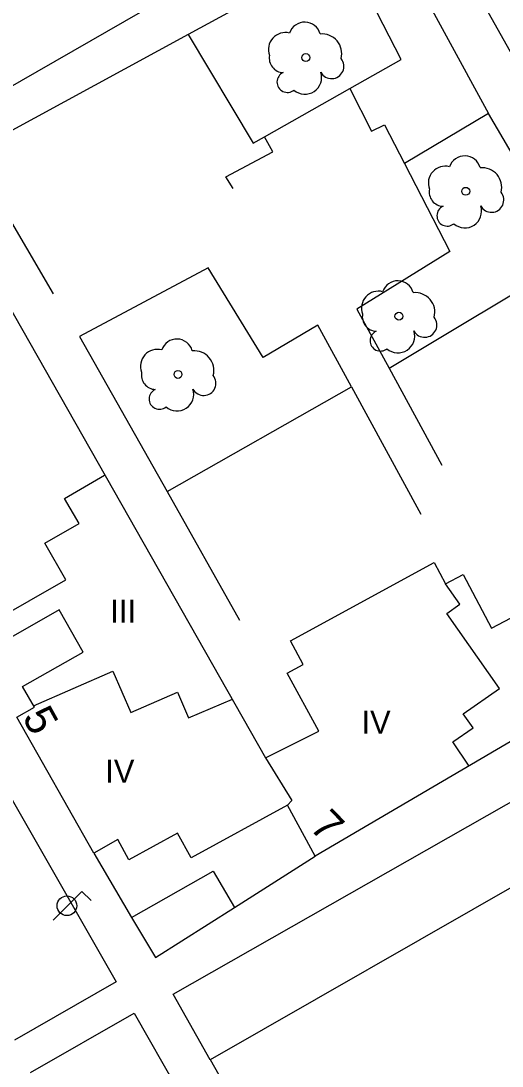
# Model space of a CAD drawing. Extents: x 282771 to 285132, y 4823109 to 4825496.
# Drawn here: x 283735.3 to 283766.5, y 4823641.9 to 4823709.7 of the extents above; entities that cross this region are included whole.
import ezdxf

# ---------------------------------------------------------------- set-up
doc = ezdxf.new("R2010")
doc.units = 0
for name, color, linetype in [('ACERA-INTERIOR', 7, 'Continuous'), ('ARBOL', 7, 'Continuous'), ('EDIFICIO', 7, 'Continuous'), ('FAROLA', 7, 'Continuous'), ('MEDIANERA', 7, 'Continuous'), ('NUM-PORTAL', 7, 'Continuous'), ('TXT-ALTURA-EDIFICIO', 7, 'Continuous'), ('ZONA-VERDE', 7, 'Continuous')]:
    doc.layers.add(name, color=color, linetype=linetype)

msp = doc.modelspace()

# ---------------------------------------------------------------- linework, layer by layer
at = {"layer": 'ACERA-INTERIOR'}
for points in [[(283760.017, 4823714.081), (283765.64, 4823703.742)], [(283746.148, 4823708.866), (283732.013, 4823701.173), (283737.392, 4823692.038)], [(283756.642, 4823705.36), (283758.048, 4823702.585), (283758.894, 4823703.008), (283760.191, 4823700.481)], [(283749.062, 4823698.858), (283748.58, 4823699.624), (283751.635, 4823701.256), (283751.098, 4823702.224)], [(283759.18, 4823687.213), (283762.612, 4823680.898)], [(283756.744, 4823685.989), (283761.242, 4823677.728)], [(283744.776, 4823679.19), (283749.482, 4823670.838)], [(283747.58, 4823642.322), (283758.962, 4823622.208), (283786.649, 4823638.022), (283775.243, 4823658.175)], [(283742.475, 4823651.555), (283744.014, 4823648.938), (283749.15, 4823652.194)]]:
    msp.add_lwpolyline(points, dxfattribs=at)
at = {"layer": 'ARBOL'}
for centre in [(283753.782, 4823707.367), (283764.162, 4823698.688), (283759.822, 4823690.578), (283745.482, 4823686.798)]:
    msp.add_circle(centre, 0.255, dxfattribs=at)
for centre, radius, start, end in [((283753.712, 4823708.627), 1.038, 15.64228, 161.38435), ((283752.452, 4823707.897), 1.097, 75.4318, 200.55608), ((283754.842, 4823707.627), 1.272, 345.03273, 95.79925), ((283752.342, 4823707.327), 0.935, 168.59898, 268.13236), ((283755.452, 4823706.797), 0.797, 208.96246, 38.99103), ((283752.582, 4823705.777), 0.672, 113.73672, 309.4725), ((283753.722, 4823706.077), 1.086, 228.95447, 17.92796), ((283764.092, 4823699.948), 1.038, 15.64228, 161.38435), ((283762.832, 4823699.218), 1.097, 75.4318, 200.55608), ((283765.222, 4823698.948), 1.272, 345.03273, 95.79925), ((283762.722, 4823698.648), 0.935, 168.59898, 268.13236), ((283765.832, 4823698.118), 0.797, 208.96246, 38.99103), ((283762.962, 4823697.098), 0.672, 113.73672, 309.4725), ((283764.102, 4823697.398), 1.086, 228.95447, 17.92796), ((283759.752, 4823691.838), 1.038, 15.64228, 161.38435), ((283758.492, 4823691.108), 1.097, 75.4318, 200.55608), ((283760.882, 4823690.838), 1.272, 345.03273, 95.79925), ((283758.382, 4823690.538), 0.935, 168.59898, 268.13236), ((283761.492, 4823690.008), 0.797, 208.96246, 38.99103), ((283745.412, 4823688.058), 1.038, 15.64228, 161.38435), ((283758.622, 4823688.988), 0.672, 113.73672, 309.4725), ((283759.762, 4823689.288), 1.086, 228.95447, 17.92796), ((283744.152, 4823687.328), 1.097, 75.4318, 200.55608), ((283746.542, 4823687.058), 1.272, 345.03273, 95.79925), ((283744.042, 4823686.758), 0.935, 168.59898, 268.13236), ((283747.152, 4823686.228), 0.797, 208.96246, 38.99103), ((283744.282, 4823685.208), 0.672, 113.73672, 309.4725), ((283745.422, 4823685.508), 1.086, 228.95447, 17.92796)]:
    msp.add_arc(centre, radius, start, end, dxfattribs=at)
at = {"layer": 'EDIFICIO'}
for points in [[(283767.562, 4823706.857), (283762.582, 4823715.717), (283765.512, 4823717.367), (283764.712, 4823718.787), (283767.492, 4823720.377), (283765.782, 4823723.377), (283728.422, 4823701.918), (283751.172, 4823661.918), (283754.622, 4823663.638), (283752.572, 4823667.398), (283753.612, 4823667.968), (283752.782, 4823669.498), (283762.102, 4823674.588), (283762.852, 4823673.198), (283763.992, 4823673.808), (283765.842, 4823670.328), (283769.622, 4823672.328)], [(283772.802, 4823666.318), (283754.392, 4823655.518), (283752.592, 4823658.828), (283746.332, 4823655.408), (283745.452, 4823657.018), (283742.302, 4823655.278), (283741.572, 4823656.598), (283740.022, 4823655.728), (283735.032, 4823664.558), (283736.162, 4823665.198), (283735.402, 4823666.548), (283739.322, 4823668.768), (283737.772, 4823671.508), (283734.172, 4823669.458)]]:
    msp.add_lwpolyline(points, dxfattribs=at)
at = {"layer": 'FAROLA'}
for p, q in [((283739.252, 4823653.238), (283738.312, 4823652.308)), ((283739.842, 4823652.648), (283739.252, 4823653.238)), ((283738.312, 4823652.308), (283737.382, 4823651.368))]:
    msp.add_line(p, q, dxfattribs=at)
msp.add_circle((283738.272, 4823652.308), 0.637, dxfattribs=at)
at = {"layer": 'MEDIANERA'}
for points in [[(283733.432, 4823670.748), (283738.202, 4823673.458), (283736.832, 4823675.848), (283739.062, 4823677.128), (283738.122, 4823678.748), (283740.722, 4823680.258)], [(283764.382, 4823661.378), (283763.312, 4823662.938), (283764.632, 4823663.858), (283764.002, 4823664.768), (283766.352, 4823666.418), (283762.942, 4823671.288), (283763.782, 4823671.878), (283762.852, 4823673.198)], [(283736.102, 4823665.288), (283741.262, 4823667.538), (283742.422, 4823664.858), (283745.452, 4823666.168), (283746.172, 4823664.498), (283749.022, 4823665.718)], [(283751.172, 4823661.918), (283752.882, 4823659.138), (283752.592, 4823658.828)]]:
    msp.add_lwpolyline(points, dxfattribs=at)
at = {"layer": 'ZONA-VERDE'}
for p, q in [((283731.619, 4823664.587), (283741.472, 4823647.361)), ((283745.162, 4823646.562), (283772.871, 4823662.333)), ((283775.234, 4823658.159), (283747.57, 4823642.306)), ((283741.472, 4823647.361), (283734.87, 4823643.585)), ((283747.57, 4823642.306), (283745.162, 4823646.562)), ((283735.912, 4823641.491), (283742.632, 4823645.331)), ((283742.632, 4823645.331), (283753.252, 4823626.741))]:
    msp.add_line(p, q, dxfattribs=at)
for points in [[(283756.642, 4823705.36), (283759.962, 4823707.237), (283757.241, 4823712.575), (283756.312, 4823714.397), (283746.148, 4823708.866), (283750.353, 4823701.803), (283751.098, 4823702.224), (283756.642, 4823705.36)], [(283765.64, 4823703.742), (283760.191, 4823700.481), (283763.122, 4823694.768), (283757.102, 4823691.038), (283759.18, 4823687.213), (283771.133, 4823694.365), (283765.64, 4823703.742)], [(283744.776, 4823679.19), (283756.744, 4823685.989), (283754.562, 4823689.998), (283751.002, 4823687.888), (283747.432, 4823693.708), (283739.102, 4823689.258), (283744.776, 4823679.19)], [(283749.15, 4823652.194), (283754.392, 4823655.518), (283752.592, 4823658.828), (283746.332, 4823655.408), (283745.452, 4823657.018), (283742.302, 4823655.278), (283741.572, 4823656.598), (283740.022, 4823655.728), (283742.475, 4823651.555), (283747.772, 4823654.558), (283749.15, 4823652.194)]]:
    msp.add_lwpolyline(points, dxfattribs=at)

# ---------------------------------------------------------------- texts
at = {"layer": 'NUM-PORTAL'}
for s, rotation, p in [('5', 299.03004, (283735.344, 4823664.541)), ('7', 314.09062, (283753.953, 4823657.351))]:
    msp.add_text(s, height=2, rotation=rotation, dxfattribs=at).set_placement(p)
at = {"layer": 'TXT-ALTURA-EDIFICIO'}
for s, p in [('III', (283741.09, 4823670.678)), ('IV', (283757.393, 4823663.478)), ('IV', (283740.763, 4823660.298))]:
    msp.add_text(s, height=1.5, rotation=0.00004, dxfattribs=at).set_placement(p)

doc.saveas('drawing.dxf')
